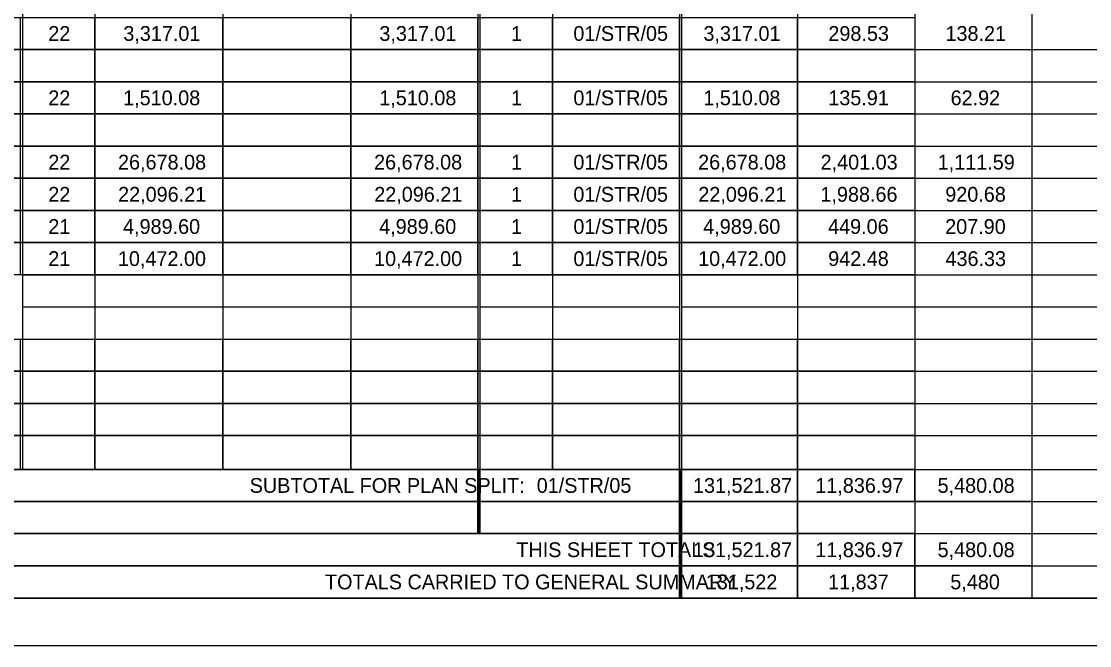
# Model space of a CAD drawing. Extents: x 0 to 34, y 0 to 22.
# Drawn here: x 9.08 to 20.36, y 0 to 6.59 of the extents above; entities that cross this region are included whole.
import ezdxf

# ---------------------------------------------------------------- set-up
doc = ezdxf.new("R2010")
doc.units = 0
for name, color, linetype in [('Default', 7, 'Continuous'), ('SH_Border', 7, 'Continuous'), ('SH_Cut_Line', 7, 'Continuous')]:
    doc.layers.add(name, color=color, linetype=linetype)

msp = doc.modelspace()

# ---------------------------------------------------------------- linework, layer by layer
at = {"layer": 'Default'}
for p, q in [((9.095, 12.819), (9.095, 1.862)), ((13.903, 12.819), (13.903, 1.183)), ((13.925, 12.819), (13.925, 1.183)), ((16.03, 12.819), (16.03, 0.503)), ((16.052, 12.819), (16.052, 0.503)), ((17.278, 12.819), (17.278, 0.503)), ((18.514, 12.819), (18.514, 0.503)), ((19.751, 12.819), (19.751, 0.503)), ((9.859, 12.378), (9.859, 1.862)), ((11.211, 12.378), (11.211, 1.862)), ((12.562, 12.378), (12.562, 1.862)), ((14.689, 12.378), (14.689, 1.862)), ((9.095, 6.296), (13.903, 6.296)), ((13.925, 6.296), (16.03, 6.296)), ((16.052, 6.296), (32, 6.296)), ((9.095, 5.956), (13.903, 5.956)), ((13.925, 5.956), (16.03, 5.956)), ((16.052, 5.956), (32, 5.956)), ((9.095, 5.617), (13.903, 5.617)), ((13.925, 5.617), (16.03, 5.617)), ((16.052, 5.617), (32, 5.617)), ((9.095, 5.277), (13.903, 5.277)), ((13.925, 5.277), (16.03, 5.277)), ((16.052, 5.277), (32, 5.277)), ((9.095, 4.937), (13.903, 4.937)), ((13.925, 4.937), (16.03, 4.937)), ((16.052, 4.937), (32, 4.937)), ((9.095, 4.597), (13.903, 4.597)), ((13.925, 4.597), (16.03, 4.597)), ((16.052, 4.597), (32, 4.597)), ((9.095, 4.258), (13.903, 4.258)), ((13.925, 4.258), (16.03, 4.258)), ((16.052, 4.258), (32, 4.258)), ((9.095, 3.918), (13.903, 3.918)), ((13.925, 3.918), (16.03, 3.918)), ((16.052, 3.918), (32, 3.918)), ((9.095, 3.578), (13.903, 3.578)), ((13.925, 3.578), (16.03, 3.578)), ((16.052, 3.578), (32, 3.578)), ((9.095, 3.238), (13.903, 3.238)), ((13.925, 3.238), (16.03, 3.238)), ((16.052, 3.238), (32, 3.238)), ((9.095, 2.899), (13.903, 2.899)), ((13.925, 2.899), (16.03, 2.899)), ((16.052, 2.899), (32, 2.899)), ((9.095, 2.559), (13.903, 2.559)), ((13.925, 2.559), (16.03, 2.559)), ((16.052, 2.559), (32, 2.559)), ((9.095, 2.219), (13.903, 2.219)), ((13.925, 2.219), (16.03, 2.219)), ((16.052, 2.219), (32, 2.219)), ((1.5, 1.862), (9.095, 1.862)), ((9.073, 1.862), (13.903, 1.862)), ((13.925, 1.862), (16.03, 1.862)), ((16.052, 1.862), (32, 1.862)), ((1.5, 1.523), (13.903, 1.523)), ((13.925, 1.523), (16.03, 1.523)), ((16.052, 1.523), (32, 1.523)), ((1.5, 1.183), (13.925, 1.183)), ((13.903, 1.183), (16.03, 1.183)), ((16.052, 1.183), (32, 1.183)), ((1.5, 0.843), (16.03, 0.843)), ((16.052, 0.843), (32, 0.843)), ((1.5, 0.503), (16.052, 0.503)), ((16.03, 0.503), (32, 0.503))]:
    msp.add_line(p, q, dxfattribs=at)
for points in [[(7.847, 6.636), (9.095, 6.636), (9.095, 6.296), (7.847, 6.296)], [(9.073, 6.636), (9.859, 6.636), (9.859, 6.296), (9.073, 6.296)], [(9.859, 6.636), (11.211, 6.636), (11.211, 6.296), (9.859, 6.296)], [(11.211, 6.636), (12.562, 6.636), (12.562, 6.296), (11.211, 6.296)], [(12.562, 6.636), (13.925, 6.636), (13.925, 6.296), (12.562, 6.296)], [(13.903, 6.636), (14.689, 6.636), (14.689, 6.296), (13.903, 6.296)], [(14.689, 6.636), (16.052, 6.636), (16.052, 6.296), (14.689, 6.296)], [(16.03, 6.636), (17.278, 6.636), (17.278, 6.296), (16.03, 6.296)], [(17.278, 6.636), (18.514, 6.636), (18.514, 6.296), (17.278, 6.296)], [(7.847, 6.296), (9.095, 6.296), (9.095, 5.956), (7.847, 5.956)], [(9.073, 6.296), (9.859, 6.296), (9.859, 5.956), (9.073, 5.956)], [(9.859, 6.296), (11.211, 6.296), (11.211, 5.956), (9.859, 5.956)], [(11.211, 6.296), (12.562, 6.296), (12.562, 5.956), (11.211, 5.956)], [(12.562, 6.296), (13.925, 6.296), (13.925, 5.956), (12.562, 5.956)], [(13.903, 6.296), (14.689, 6.296), (14.689, 5.956), (13.903, 5.956)], [(14.689, 6.296), (16.052, 6.296), (16.052, 5.956), (14.689, 5.956)], [(16.03, 6.296), (17.278, 6.296), (17.278, 5.956), (16.03, 5.956)], [(17.278, 6.296), (18.514, 6.296), (18.514, 5.956), (17.278, 5.956)], [(7.847, 5.956), (9.095, 5.956), (9.095, 5.617), (7.847, 5.617)], [(9.073, 5.956), (9.859, 5.956), (9.859, 5.617), (9.073, 5.617)], [(9.859, 5.956), (11.211, 5.956), (11.211, 5.617), (9.859, 5.617)], [(11.211, 5.956), (12.562, 5.956), (12.562, 5.617), (11.211, 5.617)], [(12.562, 5.956), (13.925, 5.956), (13.925, 5.617), (12.562, 5.617)], [(13.903, 5.956), (14.689, 5.956), (14.689, 5.617), (13.903, 5.617)], [(14.689, 5.956), (16.052, 5.956), (16.052, 5.617), (14.689, 5.617)], [(16.03, 5.956), (17.278, 5.956), (17.278, 5.617), (16.03, 5.617)], [(17.278, 5.956), (18.514, 5.956), (18.514, 5.617), (17.278, 5.617)], [(7.847, 5.617), (9.095, 5.617), (9.095, 5.277), (7.847, 5.277)], [(9.073, 5.617), (9.859, 5.617), (9.859, 5.277), (9.073, 5.277)], [(9.859, 5.617), (11.211, 5.617), (11.211, 5.277), (9.859, 5.277)], [(11.211, 5.617), (12.562, 5.617), (12.562, 5.277), (11.211, 5.277)], [(12.562, 5.617), (13.925, 5.617), (13.925, 5.277), (12.562, 5.277)], [(13.903, 5.617), (14.689, 5.617), (14.689, 5.277), (13.903, 5.277)], [(14.689, 5.617), (16.052, 5.617), (16.052, 5.277), (14.689, 5.277)], [(16.03, 5.617), (17.278, 5.617), (17.278, 5.277), (16.03, 5.277)], [(17.278, 5.617), (18.514, 5.617), (18.514, 5.277), (17.278, 5.277)], [(7.847, 5.277), (9.095, 5.277), (9.095, 4.937), (7.847, 4.937)], [(9.073, 5.277), (9.859, 5.277), (9.859, 4.937), (9.073, 4.937)], [(9.859, 5.277), (11.211, 5.277), (11.211, 4.937), (9.859, 4.937)], [(11.211, 5.277), (12.562, 5.277), (12.562, 4.937), (11.211, 4.937)], [(12.562, 5.277), (13.925, 5.277), (13.925, 4.937), (12.562, 4.937)], [(13.903, 5.277), (14.689, 5.277), (14.689, 4.937), (13.903, 4.937)], [(14.689, 5.277), (16.052, 5.277), (16.052, 4.937), (14.689, 4.937)], [(16.03, 5.277), (17.278, 5.277), (17.278, 4.937), (16.03, 4.937)], [(17.278, 5.277), (18.514, 5.277), (18.514, 4.937), (17.278, 4.937)], [(7.847, 4.937), (9.095, 4.937), (9.095, 4.597), (7.847, 4.597)], [(9.073, 4.937), (9.859, 4.937), (9.859, 4.597), (9.073, 4.597)], [(9.859, 4.937), (11.211, 4.937), (11.211, 4.597), (9.859, 4.597)], [(11.211, 4.937), (12.562, 4.937), (12.562, 4.597), (11.211, 4.597)], [(12.562, 4.937), (13.925, 4.937), (13.925, 4.597), (12.562, 4.597)], [(13.903, 4.937), (14.689, 4.937), (14.689, 4.597), (13.903, 4.597)], [(14.689, 4.937), (16.052, 4.937), (16.052, 4.597), (14.689, 4.597)], [(16.03, 4.937), (17.278, 4.937), (17.278, 4.597), (16.03, 4.597)], [(17.278, 4.937), (18.514, 4.937), (18.514, 4.597), (17.278, 4.597)], [(7.847, 4.597), (9.095, 4.597), (9.095, 4.258), (7.847, 4.258)], [(9.073, 4.597), (9.859, 4.597), (9.859, 4.258), (9.073, 4.258)], [(9.859, 4.597), (11.211, 4.597), (11.211, 4.258), (9.859, 4.258)], [(11.211, 4.597), (12.562, 4.597), (12.562, 4.258), (11.211, 4.258)], [(12.562, 4.597), (13.925, 4.597), (13.925, 4.258), (12.562, 4.258)], [(13.903, 4.597), (14.689, 4.597), (14.689, 4.258), (13.903, 4.258)], [(14.689, 4.597), (16.052, 4.597), (16.052, 4.258), (14.689, 4.258)], [(16.03, 4.597), (17.278, 4.597), (17.278, 4.258), (16.03, 4.258)], [(17.278, 4.597), (18.514, 4.597), (18.514, 4.258), (17.278, 4.258)], [(7.847, 4.258), (9.095, 4.258), (9.095, 3.918), (7.847, 3.918)], [(9.073, 4.258), (9.859, 4.258), (9.859, 3.918), (9.073, 3.918)], [(9.859, 4.258), (11.211, 4.258), (11.211, 3.918), (9.859, 3.918)], [(11.211, 4.258), (12.562, 4.258), (12.562, 3.918), (11.211, 3.918)], [(12.562, 4.258), (13.925, 4.258), (13.925, 3.918), (12.562, 3.918)], [(13.903, 4.258), (14.689, 4.258), (14.689, 3.918), (13.903, 3.918)], [(14.689, 4.258), (16.052, 4.258), (16.052, 3.918), (14.689, 3.918)], [(16.03, 4.258), (17.278, 4.258), (17.278, 3.918), (16.03, 3.918)], [(17.278, 4.258), (18.514, 4.258), (18.514, 3.918), (17.278, 3.918)], [(7.847, 3.238), (9.095, 3.238), (9.095, 2.899), (7.847, 2.899)], [(9.073, 3.238), (9.859, 3.238), (9.859, 2.899), (9.073, 2.899)], [(9.859, 3.238), (11.211, 3.238), (11.211, 2.899), (9.859, 2.899)], [(11.211, 3.238), (12.562, 3.238), (12.562, 2.899), (11.211, 2.899)], [(12.562, 3.238), (13.925, 3.238), (13.925, 2.899), (12.562, 2.899)], [(13.903, 3.238), (14.689, 3.238), (14.689, 2.899), (13.903, 2.899)], [(14.689, 3.238), (16.052, 3.238), (16.052, 2.899), (14.689, 2.899)], [(16.03, 3.238), (17.278, 3.238), (17.278, 2.899), (16.03, 2.899)], [(17.278, 3.238), (18.514, 3.238), (18.514, 2.899), (17.278, 2.899)], [(7.847, 2.899), (9.095, 2.899), (9.095, 2.559), (7.847, 2.559)], [(9.073, 2.899), (9.859, 2.899), (9.859, 2.559), (9.073, 2.559)], [(9.859, 2.899), (11.211, 2.899), (11.211, 2.559), (9.859, 2.559)], [(11.211, 2.899), (12.562, 2.899), (12.562, 2.559), (11.211, 2.559)], [(12.562, 2.899), (13.925, 2.899), (13.925, 2.559), (12.562, 2.559)], [(13.903, 2.899), (14.689, 2.899), (14.689, 2.559), (13.903, 2.559)], [(14.689, 2.899), (16.052, 2.899), (16.052, 2.559), (14.689, 2.559)], [(16.03, 2.899), (17.278, 2.899), (17.278, 2.559), (16.03, 2.559)], [(17.278, 2.899), (18.514, 2.899), (18.514, 2.559), (17.278, 2.559)], [(7.847, 2.559), (9.095, 2.559), (9.095, 2.219), (7.847, 2.219)], [(9.073, 2.559), (9.859, 2.559), (9.859, 2.219), (9.073, 2.219)], [(9.859, 2.559), (11.211, 2.559), (11.211, 2.219), (9.859, 2.219)], [(11.211, 2.559), (12.562, 2.559), (12.562, 2.219), (11.211, 2.219)], [(12.562, 2.559), (13.925, 2.559), (13.925, 2.219), (12.562, 2.219)], [(13.903, 2.559), (14.689, 2.559), (14.689, 2.219), (13.903, 2.219)], [(14.689, 2.559), (16.052, 2.559), (16.052, 2.219), (14.689, 2.219)], [(16.03, 2.559), (17.278, 2.559), (17.278, 2.219), (16.03, 2.219)], [(17.278, 2.559), (18.514, 2.559), (18.514, 2.219), (17.278, 2.219)], [(7.847, 2.219), (9.095, 2.219), (9.095, 1.862), (7.847, 1.862)], [(9.073, 2.219), (9.859, 2.219), (9.859, 1.862), (9.073, 1.862)], [(9.859, 2.219), (11.211, 2.219), (11.211, 1.862), (9.859, 1.862)], [(11.211, 2.219), (12.562, 2.219), (12.562, 1.862), (11.211, 1.862)], [(12.562, 2.219), (13.925, 2.219), (13.925, 1.862), (12.562, 1.862)], [(13.903, 2.219), (14.689, 2.219), (14.689, 1.862), (13.903, 1.862)], [(14.689, 2.219), (16.052, 2.219), (16.052, 1.862), (14.689, 1.862)], [(16.03, 2.219), (17.278, 2.219), (17.278, 1.862), (16.03, 1.862)], [(17.278, 2.219), (18.514, 2.219), (18.514, 1.862), (17.278, 1.862)], [(1.5, 1.862), (13.914, 1.862), (13.914, 1.523), (1.5, 1.523)], [(13.903, 1.862), (16.041, 1.862), (16.041, 1.523), (13.903, 1.523)], [(16.03, 1.862), (17.278, 1.862), (17.278, 1.523), (16.03, 1.523)], [(17.278, 1.862), (18.514, 1.862), (18.514, 1.523), (17.278, 1.523)], [(18.514, 1.862), (19.751, 1.862), (19.751, 1.523), (18.514, 1.523)], [(1.5, 1.523), (13.914, 1.523), (13.914, 1.183), (1.5, 1.183)], [(13.903, 1.523), (16.041, 1.523), (16.041, 1.183), (13.903, 1.183)], [(16.03, 1.523), (17.278, 1.523), (17.278, 1.183), (16.03, 1.183)], [(17.278, 1.523), (18.514, 1.523), (18.514, 1.183), (17.278, 1.183)], [(1.5, 1.183), (16.041, 1.183), (16.041, 0.843), (1.5, 0.843)], [(16.03, 1.183), (17.278, 1.183), (17.278, 0.843), (16.03, 0.843)], [(17.278, 1.183), (18.514, 1.183), (18.514, 0.843), (17.278, 0.843)], [(18.514, 1.183), (19.751, 1.183), (19.751, 0.843), (18.514, 0.843)], [(1.5, 0.843), (16.041, 0.843), (16.041, 0.503), (1.5, 0.503)], [(16.03, 0.843), (17.278, 0.843), (17.278, 0.503), (16.03, 0.503)], [(17.278, 0.843), (18.514, 0.843), (18.514, 0.503), (17.278, 0.503)], [(18.514, 0.843), (19.751, 0.843), (19.751, 0.503), (18.514, 0.503)]]:
    msp.add_lwpolyline(points, close=True, dxfattribs=at)
at = {"layer": 'SH_Border'}
msp.add_lwpolyline([(1.5, 21.5), (33.5, 21.5), (33.5, 0.5), (1.5, 0.5)], close=True, dxfattribs=at)
at = {"layer": 'SH_Cut_Line'}
msp.add_lwpolyline([(0, 0), (34, 0), (34, 22), (0, 22)], close=True, dxfattribs=at)

# ---------------------------------------------------------------- texts
at = {"layer": 'Default'}
for s, height, p in [('22', 0.1563, (9.368, 6.388)), ('3,317.01', 0.1563, (10.16, 6.388)), ('3,317.01', 0.1563, (12.863, 6.388)), ('1', 0.156, (14.253, 6.388)), ('01/STR/05', 0.1563, (14.911, 6.388)), ('3,317.01', 0.1563, (16.284, 6.388)), ('298.53', 0.1563, (17.603, 6.388)), ('138.21', 0.1563, (18.839, 6.388)), ('22', 0.1563, (9.368, 5.708)), ('1,510.08', 0.1563, (10.158, 5.708)), ('1,510.08', 0.1563, (12.862, 5.708)), ('1', 0.156, (14.253, 5.708)), ('01/STR/05', 0.1563, (14.911, 5.708)), ('1,510.08', 0.1563, (16.283, 5.708)), ('135.91', 0.1563, (17.602, 5.708)), ('62.92', 0.1563, (18.893, 5.708)), ('01/STR/05', 0.1563, (14.911, 5.029)), ('22', 0.1563, (9.368, 5.029)), ('26,678.08', 0.1563, (10.104, 5.029)), ('26,678.08', 0.1563, (12.807, 5.029)), ('1', 0.156, (14.253, 5.029)), ('26,678.08', 0.1563, (16.228, 5.029)), ('2,401.03', 0.1563, (17.521, 5.029)), ('1,111.59', 0.1563, (18.757, 5.029)), ('01/STR/05', 0.1563, (14.911, 4.689)), ('22', 0.1563, (9.368, 4.689)), ('22,096.21', 0.1563, (10.105, 4.689)), ('22,096.21', 0.1563, (12.809, 4.689)), ('1', 0.156, (14.253, 4.689)), ('22,096.21', 0.1563, (16.23, 4.689)), ('1,988.66', 0.1563, (17.519, 4.689)), ('920.68', 0.1563, (18.837, 4.689)), ('01/STR/05', 0.1563, (14.911, 4.349)), ('21', 0.1563, (9.368, 4.349)), ('4,989.60', 0.1563, (10.157, 4.349)), ('4,989.60', 0.1563, (12.861, 4.349)), ('1', 0.156, (14.253, 4.349)), ('4,989.60', 0.1563, (16.282, 4.349)), ('449.06', 0.1563, (17.6, 4.349)), ('207.90', 0.1563, (18.836, 4.349)), ('01/STR/05', 0.1563, (14.911, 4.01)), ('21', 0.1563, (9.368, 4.01)), ('10,472.00', 0.1563, (10.103, 4.01)), ('10,472.00', 0.1563, (12.807, 4.01)), ('1', 0.156, (14.253, 4.01)), ('10,472.00', 0.1563, (16.228, 4.01)), ('942.48', 0.1563, (17.601, 4.01)), ('436.33', 0.1563, (18.839, 4.01)), ('SUBTOTAL FOR PLAN SPLIT:', 0.15629, (11.494, 1.614)), ('01/STR/05', 0.1563, (14.524, 1.614)), ('131,521.87', 0.1563, (16.174, 1.614)), ('11,836.97', 0.1563, (17.465, 1.614)), ('5,480.08', 0.1563, (18.756, 1.614)), ('THIS SHEET TOTALS', 0.15629, (14.309, 0.935)), ('131,521.87', 0.1563, (16.174, 0.935)), ('11,836.97', 0.1563, (17.465, 0.935)), ('5,480.08', 0.1563, (18.756, 0.935)), ('TOTALS CARRIED TO GENERAL SUMMARY', 0.15629, (12.289, 0.595)), ('131,522', 0.1563, (16.309, 0.595)), ('11,837', 0.1563, (17.6, 0.595)), ('5,480', 0.1563, (18.89, 0.595))]:
    msp.add_text(s, height=height, dxfattribs=at).set_placement(p)

doc.saveas('drawing.dxf')
